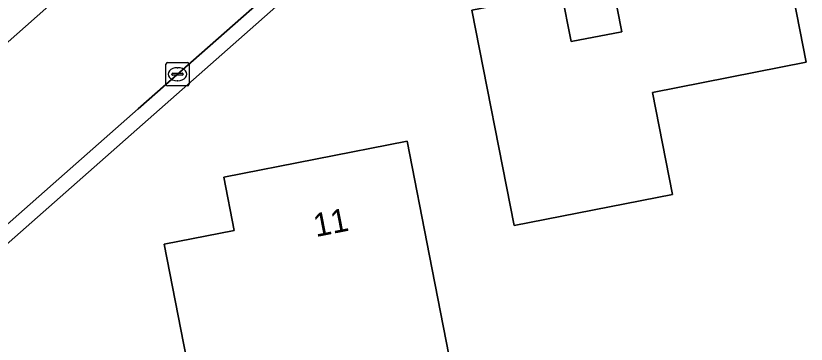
# Model space of a CAD drawing. Extents: x 157648 to 158502, y 379212 to 380938.
# Drawn here: x 158278.51 to 158312.4, y 380400.46 to 380414.54 of the extents above; entities that cross this region are included whole.
import ezdxf

# ---------------------------------------------------------------- set-up
doc = ezdxf.new("R2010")
doc.units = 0
for name, color, linetype in [('IMGEO_Erf', 7, 'Continuous'), ('IMGEO_Kolk', 7, 'Continuous'), ('IMGEO_Pand', 7, 'Continuous'), ('IMGEO_Pand_nummerreeks', 7, 'Continuous'), ('IMGEO_Rijbaan_lokaal_open', 7, 'Continuous'), ('IMGEO_Voetpad_open', 7, 'Continuous')]:
    doc.layers.add(name, color=color, linetype=linetype)

msp = doc.modelspace()

# ---------------------------------------------------------------- linework, layer by layer
at = {"layer": 'IMGEO_Erf'}
msp.add_lwpolyline([(158303.395, 380427.849), (158299.264, 380423.498), (158297.805, 380422.134), (158244.872, 380375.418), (158248.079, 380358.837), (158251.546, 380359.517), (158252.849, 380352.869), (158253.674, 380353.03), (158254.438, 380349.135), (158250.145, 380348.294), (158250.171, 380348.164), (158254.751, 380324.966), (158263.142, 380326.599), (158263.218, 380326.206), (158298.234, 380333.084)], dxfattribs=at)
for points in [[(158298.062, 380414.79), (158301.909, 380415.544), (158302.323, 380413.435), (158304.491, 380413.86), (158304.077, 380415.969), (158303.015, 380421.388), (158310.387, 380422.833), (158310.933, 380420.046), (158311.278, 380420.114), (158311.515, 380418.917), (158311.168, 380418.849), (158312.402, 380412.549), (158305.813, 380411.258), (158306.671, 380406.882), (158299.873, 380405.55)], [(158289.925, 380398.595), (158290.422, 380396.055), (158286.713, 380395.328), (158285.827, 380399.848), (158284.866, 380404.754), (158287.872, 380405.343), (158287.426, 380407.62), (158295.287, 380409.161), (158296.249, 380404.255), (158297.083, 380399.998)]]:
    msp.add_lwpolyline(points, close=True, dxfattribs=at)
at = {"layer": 'IMGEO_Kolk'}
for p, q in [((158284.942, 380411.613), (158284.942, 380412.465)), ((158285.017, 380412.539), (158285.869, 380412.539)), ((158285.43, 380412.319), (158285.455, 380412.319)), ((158285.943, 380412.465), (158285.943, 380411.613)), ((158285.201, 380412.033), (158285.201, 380412.045)), ((158285.639, 380411.996), (158285.241, 380411.996)), ((158285.244, 380412.082), (158285.642, 380412.082)), ((158285.685, 380412.045), (158285.685, 380412.033)), ((158285.453, 380411.759), (158285.428, 380411.759)), ((158285.869, 380411.539), (158285.017, 380411.539))]:
    msp.add_line(p, q, dxfattribs=at)
for points in [[(158284.942, 380411.613), (158284.942, 380412.465)], [(158285.017, 380412.539), (158285.869, 380412.539)], [(158285.943, 380412.465), (158285.943, 380411.613)], [(158285.869, 380411.539), (158285.017, 380411.539)]]:
    msp.add_lwpolyline(points, dxfattribs=at)
for centre, radius, start, end in [((158285.019, 380412.463), 0.0765, 91.552, 178.448), ((158285.019, 380412.463), 0.0765, 91.552, 178.448), ((158285.867, 380412.463), 0.0765, 1.552, 88.448), ((158285.867, 380412.463), 0.0765, 1.552, 88.448), ((158285.241, 380412.042), 0.0403, 85.8775, 175.7526), ((158285.238, 380412.032), 0.0366, 178.938, 274.7102), ((158285.642, 380412.039), 0.043, 264.8664, 352.4533), ((158285.646, 380412.044), 0.0386, 1.7309, 96.639), ((158285.019, 380411.615), 0.0765, 181.552, 268.448), ((158285.019, 380411.615), 0.0765, 181.552, 268.448), ((158285.867, 380411.615), 0.0765, 271.552, 358.448), ((158285.867, 380411.615), 0.0765, 271.552, 358.448)]:
    msp.add_arc(centre, radius, start, end, dxfattribs=at)
for centre, major_axis, ratio, start_param, end_param in [((158285.429, 380412.039), (-0.387, 0.002), 0.722429, 4.712389, 7.853982), ((158285.454, 380412.039), (-0.39, 0.002), 0.717154, 1.570796, 4.712389)]:
    msp.add_ellipse(centre, major_axis=major_axis, ratio=ratio, start_param=start_param, end_param=end_param, dxfattribs=at)
at = {"layer": 'IMGEO_Pand'}
for points in [[(158304.077, 380415.969), (158304.491, 380413.86), (158302.323, 380413.435), (158301.909, 380415.544), (158298.062, 380414.79), (158299.873, 380405.55), (158306.671, 380406.882), (158305.813, 380411.258), (158312.402, 380412.549), (158311.168, 380418.849), (158311.515, 380418.917), (158311.278, 380420.114), (158310.933, 380420.046), (158310.387, 380422.833), (158303.015, 380421.388)], [(158296.249, 380404.255), (158295.287, 380409.161), (158287.426, 380407.62), (158287.872, 380405.343), (158284.866, 380404.754), (158285.827, 380399.848), (158286.713, 380395.328), (158290.422, 380396.055), (158289.925, 380398.595), (158297.083, 380399.998)]]:
    msp.add_lwpolyline(points, close=True, dxfattribs=at)
at = {"layer": 'IMGEO_Rijbaan_lokaal_open'}
for points in [[(158275.064, 380402.899), (158280.349, 380407.546), (158283.753, 380410.559), (158293.144, 380418.837), (158296.552, 380421.825), (158297.311, 380422.499), (158300.184, 380425.29)], [(158290.558, 380424.363), (158280.432, 380415.427), (158277.036, 380412.427)]]:
    msp.add_lwpolyline(points, dxfattribs=at)
at = {"layer": 'IMGEO_Voetpad_open'}
for points in [[(158300.184, 380425.29), (158297.311, 380422.499), (158296.552, 380421.825), (158293.144, 380418.837), (158283.753, 380410.559), (158280.349, 380407.546), (158275.064, 380402.899), (158272.487, 380400.59), (158268.71, 380397.255), (158265.799, 380394.72), (158260.048, 380389.643), (158256.668, 380386.653), (158247.291, 380378.383), (158243.899, 380375.374), (158240.377, 380372.25), (158240.774, 380371.801), (158244.872, 380375.418), (158297.805, 380422.134)], [(158264.255, 380401.144), (158265.005, 380401.815), (158268.418, 380404.808), (158277.036, 380412.427), (158280.432, 380415.427), (158290.558, 380424.363)]]:
    msp.add_lwpolyline(points, dxfattribs=at)

# ---------------------------------------------------------------- texts
at = {"layer": 'IMGEO_Pand_nummerreeks'}
msp.add_text('11', height=1, rotation=11.0911, dxfattribs=at).set_placement((158291.378, 380405.052))

doc.saveas('drawing.dxf')
